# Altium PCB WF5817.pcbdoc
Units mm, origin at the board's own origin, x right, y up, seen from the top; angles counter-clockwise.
Board outline 16.7 x 16.7 mm, 2 copper layers (Top Layer, Bottom Layer); 1 components, 0 nets, 6 pads, 0 vias.
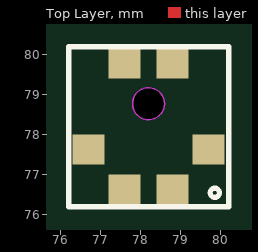
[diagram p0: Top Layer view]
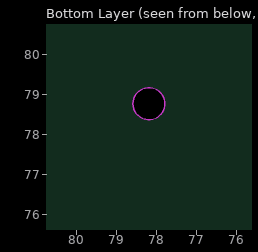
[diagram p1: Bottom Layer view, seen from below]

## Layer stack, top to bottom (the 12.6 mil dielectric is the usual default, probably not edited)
Top Layer: signal copper (thickness not stored)
Dielectric: dielectric 0.32, FR-4, Dk 4.8
Bottom Layer: signal copper (thickness not stored)

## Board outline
86.55,69.85 69.85,69.85 69.85,86.55 86.55,86.55

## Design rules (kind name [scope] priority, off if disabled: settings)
BoardOutlineClearance safeClearance [All] p0: genericclearance=0.254 ignorepadtopadclearanceinfootprint=FALSE except(0: Arc-SplitContinuation Track-SplitContinuation SMDPad-SplitContinuation THPad-SplitContinuation Via-SplitContinuation Fill-SplitContinuation Poly-SplitContinuation Region-SplitContinuation Text-SplitContinuation; 0.152: Track-CutoutEdge SMDPad-CutoutEdge THPad-CutoutEdge Via-CutoutEdge Fill-CutoutEdge Region-CutoutEdge; 0.3: Track-OutlineEdge SMDPad-OutlineEdge THPad-OutlineEdge Via-OutlineEdge Fill-OutlineEdge Region-OutlineEdge Poly-OutlineEdge Text-OutlineEdge)
Clearance safeClearance [All] p1: gap=0.178 ignorepadtopadclearanceinfootprint=FALSE except(0.152: Track-Track Track-SMDPad SMDPad-SMDPad Track-THPad SMDPad-THPad THPad-THPad Track-Via SMDPad-Via THPad-Via Via-Via Track-Fill SMDPad-Fill THPad-Fill Via-Fill Fill-Fill Track-Region SMDPad-Region THPad-Region Via-Region Fill-Region Region-Region Track-Poly SMDPad-Poly THPad-Poly Via-Poly Fill-Poly Region-Poly Poly-Poly Track-Text SMDPad-Text THPad-Text Via-Text Fill-Text Region-Text Poly-Text Text-Text; 0.175: Track-Hole SMDPad-Hole THPad-Hole Via-Hole Fill-Hole Region-Hole Poly-Hole Text-Hole Sheet-Hole; 0.3: Track-Sheet SMDPad-Sheet THPad-Sheet Via-Sheet Fill-Sheet Region-Sheet Poly-Sheet Text-Sheet)
DiffPairsRouting differentialPair [All] p1: maxuncoupledlength=10 minlimit=6 maxlimit=6 mostfreqgap=6 toplayer_minwidth=5 toplayer_prefwidth=10 toplayer_maxwidth=100 bottomlayer_minwidth=5 bottomlayer_prefwidth=10 bottomlayer_maxwidth=100
PasteMaskExpansion pasteMaskExpansion [All] p1: expansion=0
PlaneConnect innerPlane [All] p1: planeconnectstyle=Relief reliefexpansion=0.508 reliefentries=4 reliefconductorwidth=0.254 reliefairgap=0.254
PolygonConnect copperRegion [All] p1: connectstyle=Relief reliefentries=4 reliefconductorwidth=10 polygonreliefangle="90 Angle" airgapwidth=10
RoutingVias viaSize [All] p1: viastyle="Through Hole" holewidth=12.0078 minholewidth=11.811 maxholewidth=236.2204 width=24.0158 minwidth=19.685 maxwidth=393.7008
SolderMaskExpansion solderMaskExpansion [All] p1: useseparateexpansions=TRUE expansion=2 expansionbottom=2
Width trackWidth [All] p1: maxlimit=100 minlimit=5 preferedwidth=10

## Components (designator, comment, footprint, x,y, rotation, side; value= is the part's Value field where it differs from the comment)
? "WF5817" WF5817 78.2,78.2 r0 top

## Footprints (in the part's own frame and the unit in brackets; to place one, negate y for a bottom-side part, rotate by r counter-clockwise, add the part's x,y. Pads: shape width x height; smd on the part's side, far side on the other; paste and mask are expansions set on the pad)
WF5817 [mm]
  rect 0.8x0.75 smd: 1(0.595,-1.575) 2(-0.605,-1.575) 3(-1.505,-0.575) 4(-0.605,1.575) 5(0.595,1.575) 6(1.495,-0.575)
  Board Outline Layer circle w0.025: c-0.005,0.575 r0.4
  Board Outline Layer region: 0.395,0.575 0.355,0.401 0.244,0.262 0.084,0.185 -0.094,0.185 -0.254,0.262 -0.365,0.401 -0.405,0.575 -0.405,0.575 -0.365,0.749 -0.254,0.888 -0.094,0.965 0.084,0.965 0.244,0.888 0.355,0.749 0.395,0.575
  Multi-Layer board cut-out: 0.395,0.575 0.355,0.401 0.244,0.262 0.084,0.185 -0.094,0.185 -0.254,0.262 -0.365,0.401 -0.405,0.575 -0.405,0.575 -0.365,0.749 -0.254,0.888 -0.094,0.965 0.084,0.965 0.244,0.888 0.355,0.749 0.395,0.575
  silkscreen extent -2,-2 2,2

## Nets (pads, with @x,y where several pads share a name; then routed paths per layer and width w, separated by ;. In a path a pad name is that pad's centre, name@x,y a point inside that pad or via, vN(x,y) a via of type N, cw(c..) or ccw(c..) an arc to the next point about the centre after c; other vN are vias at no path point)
pads on no net: ?.1 ?.2 ?.3 ?.4 ?.5 ?.6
